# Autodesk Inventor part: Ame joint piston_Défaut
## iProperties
Shininess: 64.0
Length Units: 11269
Angle Units: 11279
Time Units: 11290
Mass Units: 11283
Length Display Precision: 3
Angle Display Precision: 2
Compacted: True
Part Number: Ame joint piston_Défaut
Document SubType Name: Modeling
Created: 2006-01
Material: Par défaut
Designer: riri
Density: 0.0
Volumn: 0.0
Area: 0.0
PropertySet Name: Model Information
Control State: 0
Master: False
Checked Out: False
Author: riri
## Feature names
1. Base1
